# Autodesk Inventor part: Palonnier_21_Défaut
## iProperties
Shininess: 64.0
Length Units: 11269
Angle Units: 11279
Time Units: 11290
Mass Units: 11283
Length Display Precision: 3
Angle Display Precision: 2
Compacted: True
Part Number: Palonnier_21_Défaut
Document SubType Name: Modeling
Created: 2006-01
Material: Par défaut
Designer: riri
Density: 0.0
Volumn: 0.0
Area: 0.0
PropertySet Name: Model Information
Control State: 0
Master: False
Checked Out: False
Author: riri
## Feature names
1. Base1
